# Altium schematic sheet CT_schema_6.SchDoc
size 296 x 258 mm
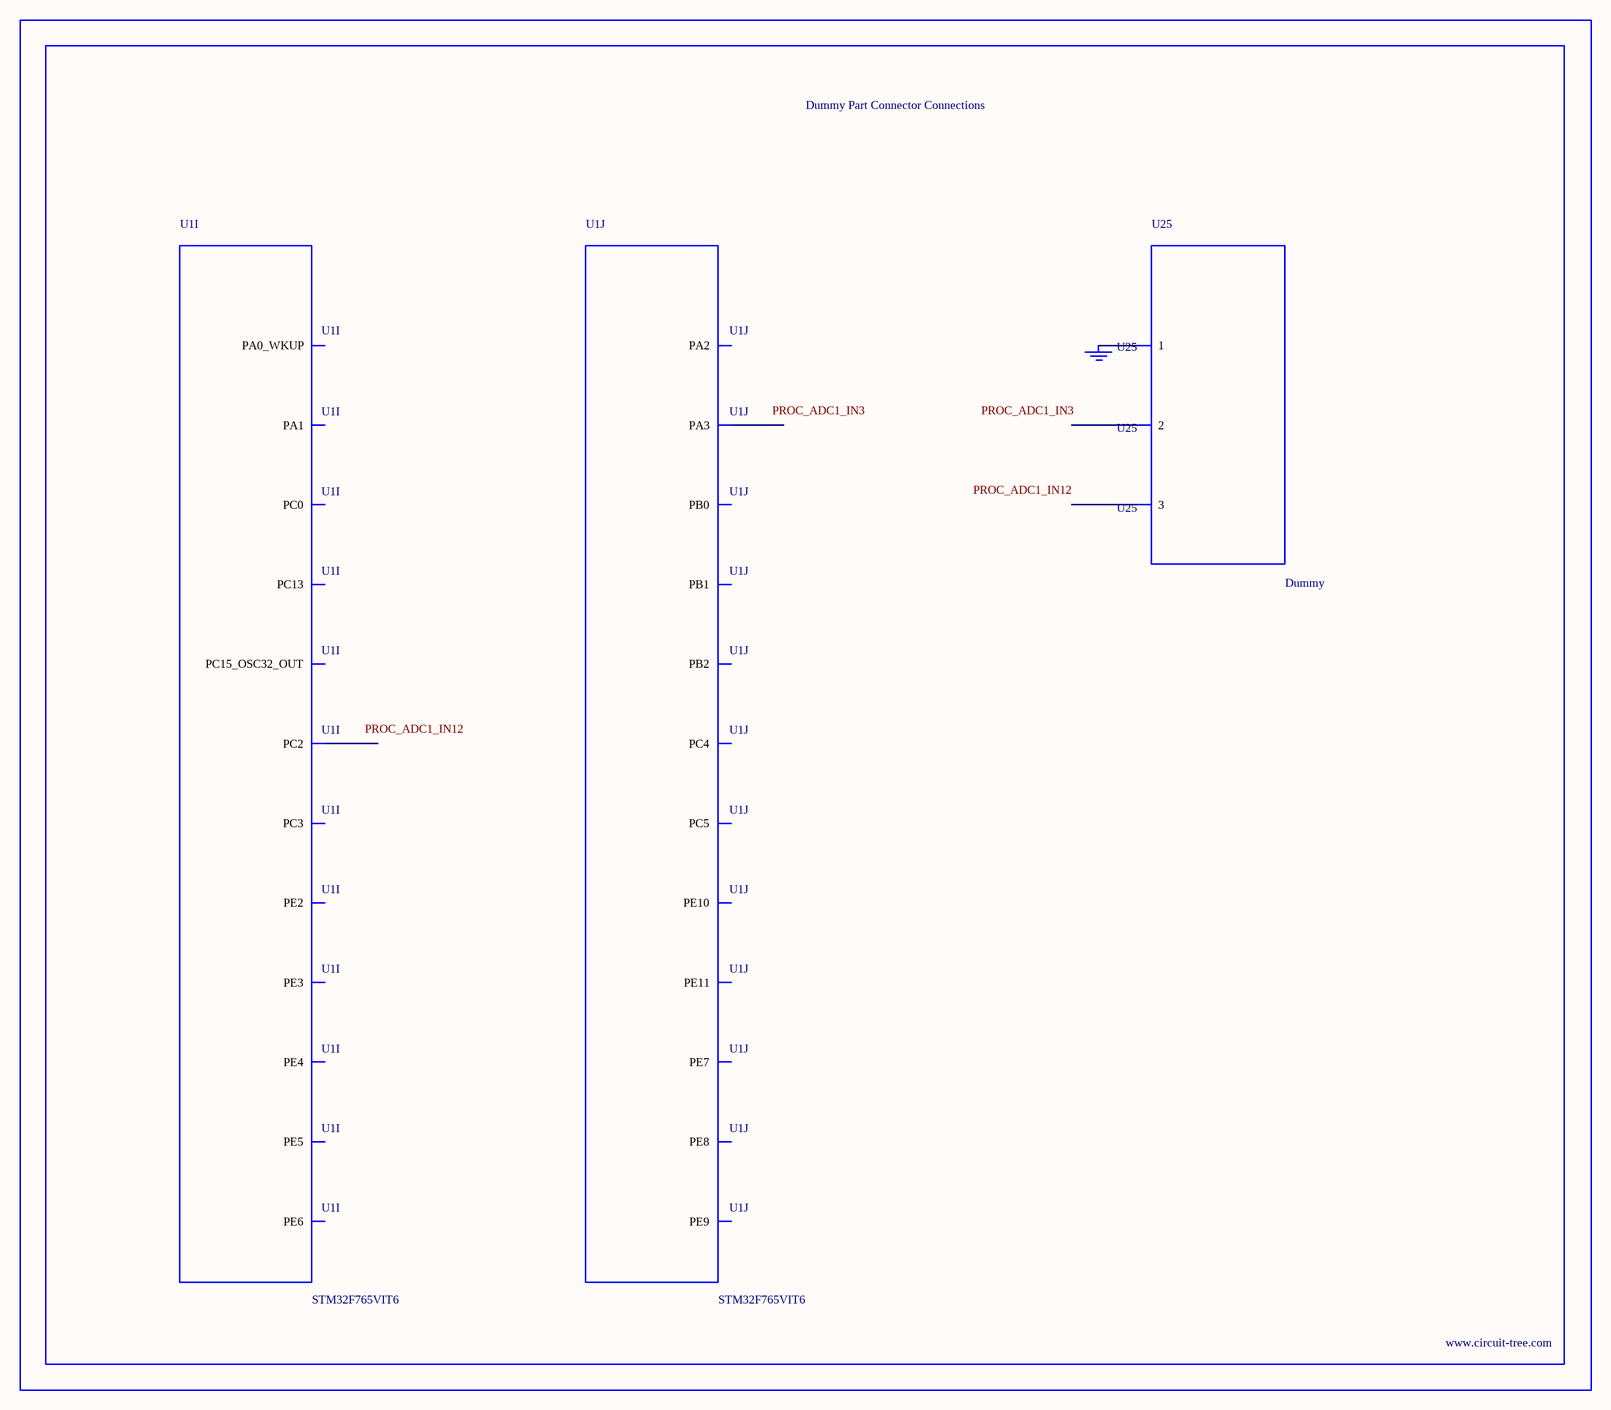
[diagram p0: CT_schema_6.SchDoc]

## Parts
BORDER5  (no value)
GND_INSTANCE_5_0  (no value)
U1  STM32F765VIT6  [LQFP100]  (parts I,J of 10)
U25  Dummy  [DUMMY_PACKAGE_213]

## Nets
NetGND_INSTANCE_5_0_0: GND_INSTANCE_5_0.0(GND) U25.1

Not connected (* = marked no-connect by the designer): U1 1(PE2) 2(PE3) 3(PE4) 4(PE5) 5(PE6) 7(PC13) 9(PC15_OSC32_OUT) 15(PC0) 17(PC2) 18(PC3) 22(PA0_WKUP) 23(PA1) 24(PA2) 25(PA3) 32(PC4) 33(PC5) 34(PB0) 35(PB1) 36(PB2) 37(PE7) 38(PE8) 39(PE9) 40(PE10) 41(PE11); U25 2 3

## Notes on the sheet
- Labels drawn without touching a wire or pin: PROC_ADC1_IN3, PROC_ADC1_IN12

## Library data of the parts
BORDER5 = BORDER_PAGE5
GND_INSTANCE_5_0 = GND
